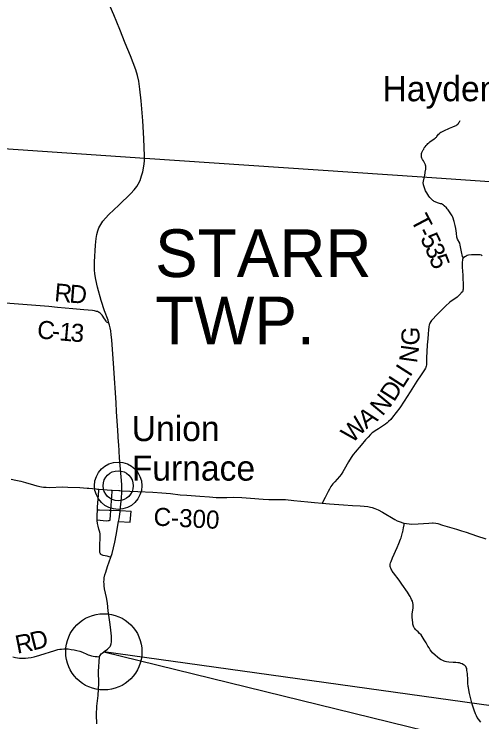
# Model space of a CAD drawing. Extents: x 0 to 34, y 0 to 22.
# Drawn here: x 5.066 to 6.535, y 17.181 to 19.405 of the extents above; entities that cross this region are included whole.
import ezdxf

# ---------------------------------------------------------------- set-up
doc = ezdxf.new("R2010")
doc.units = 0
for name, color, linetype in [('Default', 7, 'Continuous'), ('GM_X_County_Road', 7, 'Continuous'), ('GM_X_County_Road_Text', 7, 'Continuous'), ('GM_X_State_Route', 7, 'Continuous'), ('GM_X_Township_Road', 7, 'Continuous'), ('GM_X_Township_Road_Text', 7, 'Continuous'), ('GM_X_Township_Text', 7, 'Continuous'), ('GM_X_Unincorporated', 7, 'Continuous'), ('GM_X_Unincorporated_Location', 7, 'Continuous'), ('GM_X_Unincorporated_Text', 7, 'Continuous'), ('SH_Text', 7, 'Continuous')]:
    doc.layers.add(name, color=color, linetype=linetype)

msp = doc.modelspace()

# ---------------------------------------------------------------- linework, layer by layer
at = {"layer": 'Default'}
msp.add_circle((5.3474, 17.401), 0.1198, dxfattribs=at)
at = {"layer": 'GM_X_County_Road'}
for points in [[(5.3635, 18.4338), (5.3607, 18.4347), (5.3579, 18.4362), (5.3558, 18.4383), (5.3542, 18.4406), (5.3524, 18.4432), (5.3478, 18.4512), (5.3445, 18.4565), (5.3426, 18.4591), (5.3405, 18.4615), (5.3383, 18.4637), (5.3358, 18.4657), (5.3332, 18.4675), (5.3303, 18.469), (5.3274, 18.4702), (5.3244, 18.4712), (5.3182, 18.4725), (5.312, 18.4734), (5.2841, 18.4757), (5.2501, 18.4787), (5.2024, 18.4836), (5.1747, 18.4862), (5.1065, 18.4913), (5.0385, 18.4973)], [(5.0562, 17.9434), (5.0713, 17.9404), (5.0864, 17.9372), (5.1014, 17.9336), (5.1261, 17.9261), (5.1367, 17.9231), (5.1519, 17.9197), (5.1584, 17.9187), (5.1665, 17.9181), (5.1756, 17.918), (5.2191, 17.9191), (5.2346, 17.9189), (5.2719, 17.9171), (5.2953, 17.9154), (5.2998, 17.9151), (5.3236, 17.9132)], [(5.3236, 17.9132), (5.3275, 17.9128), (5.3314, 17.9125), (5.3701, 17.9094), (5.3736, 17.9092), (5.3948, 17.9077), (5.3979, 17.9076), (5.404, 17.9075)], [(5.404, 17.9075), (5.4544, 17.9054), (5.5008, 17.9029), (5.5299, 17.9008), (5.5569, 17.8982), (5.5876, 17.8949), (5.6083, 17.8932), (5.6485, 17.8901), (5.6793, 17.8877), (5.7002, 17.8866), (5.734, 17.8866), (5.7557, 17.8867), (5.7806, 17.8861), (5.8085, 17.8843), (5.8476, 17.8809), (5.8659, 17.8802), (5.904, 17.8801), (5.9184, 17.8797), (5.9446, 17.8771), (5.988, 17.8724), (6.009, 17.8706), (6.0326, 17.8686), (6.056, 17.8666), (6.1003, 17.8629), (6.1282, 17.8611), (6.1529, 17.8599), (6.1652, 17.8592), (6.1764, 17.858), (6.1849, 17.8562), (6.1905, 17.8546), (6.1985, 17.8517), (6.2092, 17.8469), (6.2226, 17.84), (6.2612, 17.817), (6.2691, 17.813), (6.2776, 17.8095), (6.2864, 17.8069), (6.291, 17.8058), (6.3136, 17.8025), (6.335, 17.8028), (6.3679, 17.8058), (6.3792, 17.8064), (6.3814, 17.8064), (6.39, 17.8053), (6.3962, 17.804), (6.4109, 17.7996), (6.4256, 17.7948), (6.4405, 17.7905), (6.4549, 17.7862), (6.4704, 17.7813), (6.485, 17.7766), (6.5182, 17.7655), (6.5469, 17.7559)]]:
    msp.add_lwpolyline(points, dxfattribs=at)
at = {"layer": 'GM_X_State_Route'}
for points in [[(5.3635, 18.4338), (5.3606, 18.4436), (5.3497, 18.4727), (5.3393, 18.5052), (5.3276, 18.547), (5.322, 18.5711), (5.3192, 18.5894), (5.3182, 18.6016), (5.3177, 18.6079), (5.3177, 18.6188), (5.3176, 18.6264), (5.3213, 18.679), (5.3232, 18.7006), (5.3254, 18.7128), (5.3287, 18.7246), (5.3321, 18.7332), (5.3377, 18.7441), (5.3446, 18.7544), (5.3524, 18.7639), (5.363, 18.7752), (5.3945, 18.805), (5.4325, 18.8418), (5.4431, 18.8532), (5.4507, 18.8631), (5.4556, 18.8712), (5.461, 18.8825), (5.4662, 18.8972), (5.4694, 18.9092), (5.4729, 18.9277), (5.4746, 18.9432), (5.475, 18.9588), (5.4727, 19.0146), (5.4694, 19.0705), (5.4647, 19.1324), (5.4606, 19.1695), (5.457, 19.1942), (5.453, 19.2124), (5.4476, 19.2303), (5.4313, 19.274), (5.4148, 19.3143), (5.3973, 19.3574), (5.3784, 19.4034), (5.2915, 19.6027)], [(5.3875, 18.1559), (5.3858, 18.1838), (5.3789, 18.2923), (5.3724, 18.3821), (5.3708, 18.3975), (5.3691, 18.4098), (5.3674, 18.4189), (5.3652, 18.4279), (5.3644, 18.4309), (5.3635, 18.4338)], [(5.371, 17.4484), (5.371, 17.4505), (5.3697, 17.4689), (5.3677, 17.4873), (5.3645, 17.5088), (5.3615, 17.5303), (5.3584, 17.554), (5.3554, 17.5721), (5.35, 17.5995), (5.3486, 17.6086), (5.348, 17.6148), (5.3479, 17.6211), (5.3481, 17.6273), (5.3488, 17.6335), (5.3508, 17.6427), (5.3533, 17.6517), (5.3592, 17.6694), (5.3696, 17.6985), (5.3733, 17.7102), (5.378, 17.728), (5.3822, 17.746), (5.3864, 17.7673), (5.3939, 17.8108), (5.3953, 17.8193), (5.3982, 17.8407), (5.3987, 17.8455), (5.4027, 17.8853), (5.4039, 17.902), (5.404, 17.9075), (5.4041, 17.9112), (5.4035, 17.9267), (5.4019, 17.9515), (5.397, 18.0103), (5.3941, 18.0524), (5.3935, 18.0598), (5.391, 18.097), (5.3875, 18.1559)], [(5.3254, 17.1744), (5.3247, 17.2033), (5.3259, 17.2302), (5.3294, 17.2639), (5.3314, 17.303), (5.3308, 17.3387), (5.3333, 17.3855), (5.3338, 17.3866), (5.3355, 17.3893), (5.3394, 17.3942), (5.3417, 17.3965), (5.3466, 17.4004), (5.3483, 17.4016), (5.3591, 17.4096), (5.3614, 17.4114), (5.3635, 17.4131), (5.3656, 17.4153), (5.3673, 17.4176), (5.3687, 17.4203), (5.3697, 17.4231), (5.3704, 17.426), (5.3711, 17.4321), (5.3713, 17.4382), (5.371, 17.4484)]]:
    msp.add_lwpolyline(points, dxfattribs=at)
at = {"layer": 'GM_X_Township_Road'}
msp.add_line((5.3987, 17.8455), (5.4335, 17.843), dxfattribs=at)
for points in [[(6.4767, 18.6393), (6.4742, 18.6441), (6.4711, 18.6586), (6.467, 18.6791), (6.4654, 18.6855), (6.4585, 18.6983), (6.4565, 18.7042), (6.4546, 18.7174), (6.4525, 18.732), (6.4508, 18.7408), (6.4474, 18.7537), (6.4433, 18.767), (6.4411, 18.7711), (6.4367, 18.7778), (6.4284, 18.7902), (6.4254, 18.7939), (6.4232, 18.7966), (6.4167, 18.8024), (6.4138, 18.8046), (6.4074, 18.8087), (6.4046, 18.8096), (6.3955, 18.8126), (6.3933, 18.8134), (6.3903, 18.8144), (6.3877, 18.8154), (6.3851, 18.8168), (6.3828, 18.8183), (6.3808, 18.82), (6.3782, 18.8221), (6.3748, 18.8255), (6.3716, 18.8295), (6.3683, 18.8337), (6.365, 18.8383), (6.3619, 18.8432), (6.3595, 18.8472), (6.358, 18.8502), (6.3567, 18.8531), (6.3553, 18.8563), (6.3532, 18.8622), (6.3522, 18.8655), (6.3514, 18.8684), (6.3509, 18.8708), (6.3506, 18.873), (6.3505, 18.8751), (6.3506, 18.8772), (6.3509, 18.8796), (6.3513, 18.8821), (6.3519, 18.8845), (6.3552, 18.8994), (6.358, 18.9146), (6.3584, 18.9174), (6.3586, 18.9203), (6.3587, 18.9225), (6.3587, 18.9246), (6.3586, 18.9263), (6.3583, 18.9282), (6.3579, 18.9299), (6.3575, 18.9313), (6.351, 18.9443), (6.3483, 18.9484), (6.3471, 18.9505), (6.346, 18.9531), (6.3453, 18.9557), (6.3449, 18.9584), (6.3448, 18.9612), (6.3448, 18.9639), (6.3454, 18.967), (6.3464, 18.9702), (6.3476, 18.973), (6.3503, 18.9785), (6.3519, 18.9814), (6.3539, 18.9847), (6.3564, 18.9883), (6.3593, 18.9921), (6.3626, 18.9959), (6.3652, 18.9986), (6.3685, 19.0013), (6.3717, 19.0038), (6.3853, 19.0132), (6.3877, 19.0151), (6.3899, 19.0171), (6.3918, 19.0191), (6.3934, 19.021), (6.3989, 19.0278), (6.4011, 19.0304), (6.4031, 19.0323), (6.4057, 19.034), (6.4086, 19.0357), (6.4148, 19.0386), (6.4332, 19.0467), (6.4438, 19.0509), (6.4513, 19.0542), (6.454, 19.0556), (6.4562, 19.0572), (6.4588, 19.0595), (6.4611, 19.0621), (6.4625, 19.0643), (6.4642, 19.067), (6.466, 19.0712)], [(6.536, 18.646), (6.5332, 18.6473), (6.5291, 18.6483), (6.5224, 18.6487), (6.513, 18.6486), (6.5018, 18.6483), (6.4925, 18.6473), (6.4881, 18.6463), (6.4849, 18.645), (6.4812, 18.6426), (6.4767, 18.6393), (6.4749, 18.6371), (6.4737, 18.6338), (6.4733, 18.6309), (6.4731, 18.6268), (6.4729, 18.6103), (6.475, 18.5854), (6.4753, 18.5819), (6.4756, 18.5508), (6.4755, 18.5412), (6.4753, 18.5382), (6.475, 18.5361), (6.4745, 18.5344), (6.4735, 18.533), (6.47, 18.529), (6.4681, 18.527), (6.4659, 18.5245), (6.4614, 18.5202), (6.4567, 18.5162), (6.4343, 18.4998), (6.4209, 18.4878), (6.4058, 18.4724), (6.3926, 18.4593), (6.3792, 18.4455), (6.3761, 18.4419), (6.3743, 18.4393), (6.3713, 18.4339), (6.3702, 18.4312), (6.3693, 18.4283), (6.3679, 18.4223), (6.3667, 18.4129), (6.366, 18.4005), (6.3648, 18.3846), (6.3631, 18.3657), (6.3618, 18.344), (6.3609, 18.3257), (6.3608, 18.3169), (6.3603, 18.3035), (6.3597, 18.2987), (6.3588, 18.2958), (6.3583, 18.2947), (6.3575, 18.2928), (6.3547, 18.2875), (6.3526, 18.2844), (6.3444, 18.2718), (6.3302, 18.2516), (6.3092, 18.2177), (6.2907, 18.189), (6.2769, 18.1684), (6.266, 18.1532), (6.2545, 18.1385), (6.2483, 18.1316), (6.2416, 18.1249), (6.2371, 18.1206), (6.2324, 18.1171), (6.2224, 18.1104), (6.2101, 18.1024), (6.1994, 18.0954), (6.1951, 18.0926), (6.1901, 18.0891), (6.1851, 18.0845), (6.1771, 18.076), (6.175, 18.0738), (6.1688, 18.0669), (6.1552, 18.0502), (6.149, 18.0429), (6.1419, 18.0348), (6.1373, 18.0295), (6.1302, 18.0211), (6.1238, 18.012), (6.1158, 17.9985), (6.1024, 17.9744), (6.0978, 17.9664), (6.0927, 17.9588), (6.0872, 17.9516), (6.0798, 17.9433), (6.0726, 17.9356), (6.0667, 17.9288), (6.0603, 17.9203), (6.0556, 17.9126), (6.0516, 17.9049), (6.0429, 17.8866), (6.0326, 17.8686)], [(5.3295, 17.7955), (5.3278, 17.8045), (5.3266, 17.8137), (5.3265, 17.8158), (5.3262, 17.8199), (5.3262, 17.8291), (5.327, 17.8468), (5.3275, 17.8569), (5.3302, 17.8939), (5.3312, 17.9093), (5.3314, 17.9125)], [(5.367, 17.8146), (5.3674, 17.8158), (5.3676, 17.8179), (5.3684, 17.8299), (5.3693, 17.8465), (5.3733, 17.9051), (5.3736, 17.9092)], [(5.327, 17.8468), (5.3334, 17.8468), (5.3644, 17.8467), (5.3693, 17.8465), (5.3987, 17.8455)], [(5.3939, 17.8108), (5.4305, 17.8087), (5.4335, 17.843)], [(5.3265, 17.8158), (5.3457, 17.8139), (5.3548, 17.8132), (5.361, 17.8134), (5.3641, 17.8137), (5.367, 17.8146)], [(5.3696, 17.6985), (5.3639, 17.7), (5.3579, 17.7014), (5.3458, 17.7035), (5.3428, 17.7045), (5.3401, 17.7059), (5.3379, 17.708), (5.3362, 17.7106), (5.3352, 17.7135), (5.3348, 17.7166), (5.3348, 17.7196), (5.3353, 17.7382), (5.336, 17.7567), (5.336, 17.7659), (5.3355, 17.7716), (5.3344, 17.7776), (5.3319, 17.7866), (5.3295, 17.7955)], [(6.5315, 17.1798), (6.5239, 17.1896), (6.5204, 17.1947), (6.5174, 17.2001), (6.5149, 17.2058), (6.5109, 17.2174), (6.5044, 17.2362), (6.4996, 17.2537), (6.4958, 17.2699), (6.4934, 17.2815), (6.4923, 17.2893), (6.4918, 17.2924), (6.4909, 17.302), (6.4906, 17.3114), (6.4904, 17.3185), (6.4899, 17.3266), (6.4892, 17.3328), (6.4887, 17.3375), (6.4879, 17.3433), (6.487, 17.3485), (6.4856, 17.3518), (6.4839, 17.3546), (6.4819, 17.357), (6.4796, 17.359), (6.4773, 17.3605), (6.4724, 17.3632), (6.4681, 17.3648), (6.464, 17.366), (6.4594, 17.3666), (6.4534, 17.367), (6.4445, 17.3676), (6.4308, 17.3685), (6.4235, 17.3692), (6.4195, 17.3701), (6.4159, 17.3715), (6.4118, 17.3735), (6.407, 17.3761), (6.4017, 17.3793), (6.3951, 17.384), (6.3875, 17.39), (6.38, 17.3976), (6.376, 17.4024), (6.3726, 17.4072), (6.3689, 17.4134), (6.3653, 17.4193), (6.3598, 17.4292), (6.3538, 17.4387), (6.3471, 17.4493), (6.3435, 17.4543), (6.3392, 17.459), (6.3345, 17.4636), (6.3298, 17.4678), (6.3263, 17.4713), (6.3237, 17.4747), (6.3222, 17.4768), (6.3212, 17.4787), (6.3201, 17.4812), (6.319, 17.4843), (6.3182, 17.4881), (6.3176, 17.4933), (6.317, 17.5007), (6.316, 17.5097), (6.3158, 17.5152), (6.3159, 17.5205), (6.3165, 17.5257), (6.3176, 17.5326), (6.3184, 17.5387), (6.3187, 17.5424), (6.3187, 17.5457), (6.3185, 17.5495), (6.3177, 17.5549), (6.3163, 17.56), (6.314, 17.5653), (6.3113, 17.5707), (6.3091, 17.5747), (6.3072, 17.5781), (6.3008, 17.5884), (6.2835, 17.6138), (6.275, 17.6266), (6.2572, 17.6497), (6.2534, 17.6546), (6.2514, 17.6572), (6.2494, 17.6606), (6.2483, 17.6635), (6.2475, 17.666), (6.247, 17.6692), (6.2467, 17.6723), (6.247, 17.6762), (6.2478, 17.6803), (6.2494, 17.6848), (6.2538, 17.6961), (6.2595, 17.7084), (6.2637, 17.7171), (6.2689, 17.7292), (6.274, 17.7415), (6.2792, 17.7552), (6.2807, 17.7591), (6.2859, 17.7761), (6.2865, 17.7784), (6.2888, 17.7906), (6.2901, 17.7998), (6.291, 17.8058)], [(5.0613, 17.3856), (5.0702, 17.3831), (5.0762, 17.382), (5.0824, 17.3813), (5.0916, 17.381), (5.1009, 17.3814), (5.1102, 17.3822), (5.1194, 17.3835), (5.1285, 17.3855), (5.1464, 17.3906), (5.1937, 17.4056), (5.2027, 17.408), (5.2088, 17.4092), (5.2149, 17.4098), (5.2214, 17.4103), (5.2354, 17.4099), (5.2448, 17.4087), (5.2538, 17.4075), (5.2626, 17.4055), (5.2715, 17.4029), (5.2802, 17.3997), (5.2943, 17.3937), (5.2987, 17.392), (5.3025, 17.3905), (5.3082, 17.3887), (5.3142, 17.3874), (5.3204, 17.3865), (5.3266, 17.386), (5.3333, 17.3855)]]:
    msp.add_lwpolyline(points, dxfattribs=at)
at = {"layer": 'GM_X_Township_Text'}
msp.add_lwpolyline([(8.7763, 18.7365), (7.7116, 18.8006), (7.6851, 18.802), (7.2653, 18.8305), (6.9608, 18.8511), (6.9477, 18.852), (6.9018, 18.8551), (6.7713, 18.864), (6.3469, 18.8928), (5.4766, 18.9518), (4.3125, 19.0308), (4.2973, 19.0318), (4.1694, 19.0405), (3.3833, 19.0938), (3.2714, 17.3671), (3.2279, 16.6952), (3.1822, 15.9898), (3.1607, 15.6594), (3.1102, 14.8789), (3.0682, 14.2309), (3.0665, 14.2054)], dxfattribs=at)
at = {"layer": 'GM_X_Unincorporated'}
for radius in [0.0744, 0.0472]:
    msp.add_circle((5.3924, 17.9231), radius, dxfattribs=at)
at = {"layer": 'GM_X_Unincorporated_Location'}
msp.add_line((5.3924, 17.9231), (5.3924, 17.9231), dxfattribs=at)
at = {"layer": 'SH_Text'}
msp.add_lwpolyline([(5.3474, 17.401), (9.2222, 16.4501), (9.2222, 16.8603)], close=True, dxfattribs=at)

# ---------------------------------------------------------------- texts
at = {"layer": 'GM_X_County_Road_Text'}
for s, height, rotation, p in [('R', 0.0568, 354.861, (5.1904, 18.5031)), ('D', 0.0568, 355.5266, (5.2376, 18.4989)), ('C', 0.0568, 354.7469, (5.1361, 18.3867)), ('1', 0.0568, 354.8082, (5.2058, 18.3803)), ('3', 0.0568, 355.1583, (5.2411, 18.3771)), ('-', 0.0568, 354.7518, (5.1825, 18.3824)), ('C-300', 0.05682, 356.9734, (5.5024, 17.7981))]:
    msp.add_text(s, height=height, rotation=rotation, dxfattribs=at).set_placement(p)
at = {"layer": 'GM_X_Township_Road_Text'}
for s, rotation, p in [('T', 297.8819, (6.3097, 18.7588)), ('-', 297.1899, (6.3295, 18.7214)), ('5', 295.3734, (6.3399, 18.7011)), ('3', 293.1815, (6.3547, 18.67)), ('5', 290.7905, (6.3682, 18.6384)), ('G', 88.4443, (6.338, 18.3632)), ('N', 82.0906, (6.3306, 18.3069)), ('I', 57.3905, (6.3088, 18.2623)), ('L', 57.1301, (6.2856, 18.2264)), ('D', 57.3839, (6.2587, 18.1843)), ('N', 50.2459, (6.2221, 18.1396)), ('A', 36.8014, (6.1716, 18.0997)), ('W', 45.5654, (6.1272, 18.0542)), ('D', 14.3237, (5.1242, 17.4047)), ('R', 11.2617, (5.0753, 17.3949))]:
    msp.add_text(s, height=0.0568, rotation=rotation, dxfattribs=at).set_placement(p)
at = {"layer": 'GM_X_Township_Text'}
for s, p in [('STARR', (5.5084, 18.579)), ('TWP.', (5.5084, 18.3674))]:
    msp.add_text(s, height=0.15, rotation=0, dxfattribs=at).set_placement(p)
at = {"layer": 'GM_X_Unincorporated_Text'}
for s, height, p in [('Haydenville', 0.078977, (6.2226, 19.1316)), ('Union', 0.07898, (5.4351, 18.0633)), ('Furnace', 0.07898, (5.4351, 17.9391))]:
    msp.add_text(s, height=height, rotation=0, dxfattribs=at).set_placement(p)

doc.saveas('drawing.dxf')
